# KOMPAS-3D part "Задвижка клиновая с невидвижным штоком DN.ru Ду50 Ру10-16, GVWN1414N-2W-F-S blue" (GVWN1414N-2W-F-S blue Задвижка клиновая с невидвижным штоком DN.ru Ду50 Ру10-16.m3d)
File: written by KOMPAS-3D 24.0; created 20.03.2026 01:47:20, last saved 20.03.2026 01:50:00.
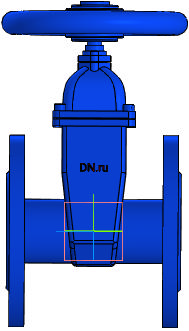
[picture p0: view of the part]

Document properties: Автор: R2D2; Полное имя файла: GVWN1414N-2W-F-S blue Задвижка клиновая с невидвижным штоком DN.ru Ду50 Ру10-16.cdw

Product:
- Part/product: Задвижка клиновая с невидвижным штоком DN.ru Ду50 Ру10-16  | designation GVWN1414N-2W-F-S blue
    Масса: 7
    Раздел спецификации: Прочие изделия
    Форматы листов документа: A2
    Примечание: D040-10579

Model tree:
1. Операция без истории:1

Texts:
  GVWN1414N-2W-F-S blue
